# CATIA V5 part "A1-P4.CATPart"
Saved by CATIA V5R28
Part number: Part4
Source: Unknown
Bounding box of the stored display mesh (mm): x -24.951 to 24.951, y -25 to 25, z -35 to 35
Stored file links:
  E:\TP Catia - Documents\Additional Exercise\Contrôle\Problem-3-Section-J\A1-P4.CATPart
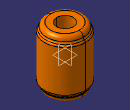
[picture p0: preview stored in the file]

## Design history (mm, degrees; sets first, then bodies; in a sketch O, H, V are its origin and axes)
Body1 (main body)
  Solid1 "Corps principal": solid without history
